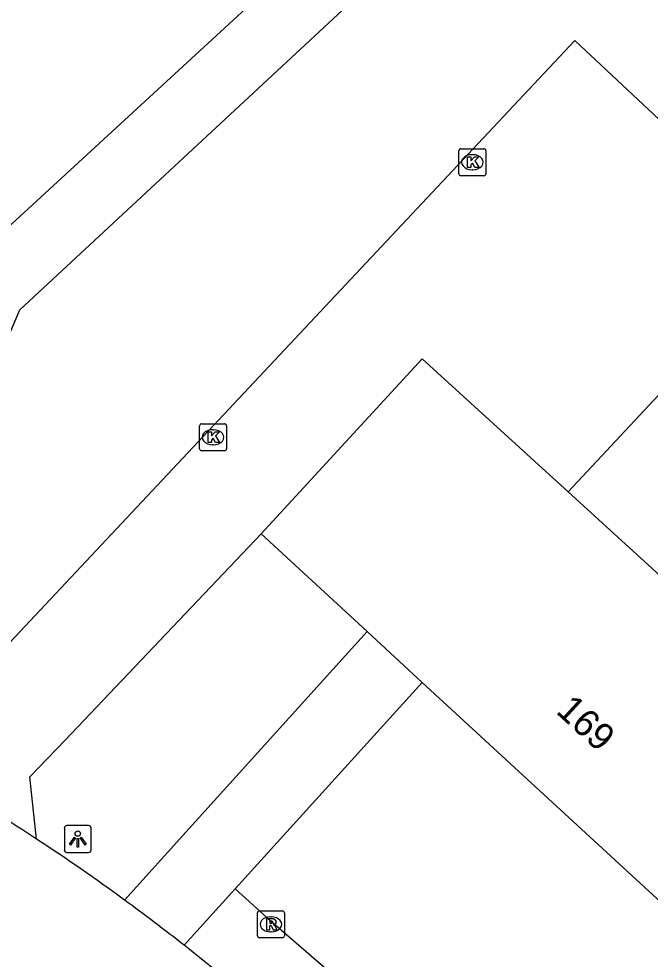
# Model space of a CAD drawing. Extents: x 160203 to 161526, y 379529 to 381797.
# Drawn here: x 160857.86 to 160881.3, y 381464.3 to 381499.19 of the extents above; entities that cross this region are included whole.
import ezdxf

# ---------------------------------------------------------------- set-up
doc = ezdxf.new("R2010")
doc.units = 0
for name, color, linetype in [('IMGEO_Grasland_overig', 7, 'Continuous'), ('IMGEO_Kolk', 7, 'Continuous'), ('IMGEO_Lichtpunt', 7, 'Continuous'), ('IMGEO_Pand', 7, 'Continuous'), ('IMGEO_Pand_nummerreeks', 7, 'Continuous'), ('IMGEO_Parkeervlak_open', 7, 'Continuous'), ('IMGEO_Rijbaan_lokaal_gesloten', 7, 'Continuous'), ('IMGEO_Rioolput', 7, 'Continuous'), ('IMGEO_Voetpad_open', 7, 'Continuous'), ('IMGEO_Waterloop', 7, 'Continuous')]:
    doc.layers.add(name, color=color, linetype=linetype)

msp = doc.modelspace()

# ---------------------------------------------------------------- linework, layer by layer
at = {"layer": 'IMGEO_Grasland_overig'}
msp.add_lwpolyline([(160865.887, 381466.901), (160867.061, 381465.849), (160874.741, 381459.219), (160875.912, 381458.343)], dxfattribs=at)
at = {"layer": 'IMGEO_Kolk'}
for p, q in [((160874.197, 381493.442), (160874.197, 381494.294)), ((160874.272, 381494.368), (160875.124, 381494.368)), ((160875.198, 381494.294), (160875.198, 381493.442)), ((160874.685, 381494.148), (160874.71, 381494.148)), ((160874.708, 381493.588), (160874.683, 381493.588)), ((160875.124, 381493.368), (160874.272, 381493.368)), ((160864.644, 381484.162), (160865.496, 381484.162)), ((160864.569, 381483.236), (160864.569, 381484.088)), ((160865.057, 381483.942), (160865.082, 381483.942)), ((160865.57, 381484.088), (160865.57, 381483.236)), ((160865.496, 381483.162), (160864.644, 381483.162)), ((160865.08, 381483.382), (160865.055, 381483.382))]:
    msp.add_line(p, q, dxfattribs=at)
for points in [[(160874.197, 381493.442), (160874.197, 381494.294)], [(160874.272, 381494.368), (160875.124, 381494.368)], [(160875.198, 381494.294), (160875.198, 381493.442)], [(160874.518, 381494.068), (160874.641, 381494.068), (160874.641, 381493.917), (160874.771, 381494.068), (160874.935, 381494.068), (160874.789, 381493.917), (160874.942, 381493.668), (160874.79, 381493.668), (160874.705, 381493.832), (160874.641, 381493.765), (160874.641, 381493.668), (160874.518, 381493.668), (160874.518, 381494.068)], [(160875.124, 381493.368), (160874.272, 381493.368)], [(160864.644, 381484.162), (160865.496, 381484.162)], [(160864.569, 381483.236), (160864.569, 381484.088)], [(160864.89, 381483.862), (160865.013, 381483.862), (160865.013, 381483.711), (160865.143, 381483.862), (160865.307, 381483.862), (160865.161, 381483.711), (160865.314, 381483.462), (160865.162, 381483.462), (160865.077, 381483.626), (160865.013, 381483.559), (160865.013, 381483.462), (160864.89, 381483.462), (160864.89, 381483.862)], [(160865.57, 381484.088), (160865.57, 381483.236)], [(160865.496, 381483.162), (160864.644, 381483.162)]]:
    msp.add_lwpolyline(points, dxfattribs=at)
for centre, start, end in [((160874.274, 381494.292), 91.552, 178.448), ((160874.274, 381494.292), 91.552, 178.448), ((160875.122, 381494.292), 1.552, 88.448), ((160875.122, 381494.292), 1.552, 88.448), ((160874.274, 381493.444), 181.552, 268.448), ((160874.274, 381493.444), 181.552, 268.448), ((160875.122, 381493.444), 271.552, 358.448), ((160875.122, 381493.444), 271.552, 358.448), ((160864.646, 381484.086), 91.552, 178.448), ((160864.646, 381484.086), 91.552, 178.448), ((160865.494, 381484.086), 1.552, 88.448), ((160865.494, 381484.086), 1.552, 88.448), ((160864.646, 381483.238), 181.552, 268.448), ((160864.646, 381483.238), 181.552, 268.448), ((160865.494, 381483.238), 271.552, 358.448), ((160865.494, 381483.238), 271.552, 358.448)]:
    msp.add_arc(centre, 0.0765, start, end, dxfattribs=at)
for centre, major_axis, ratio, start_param, end_param in [((160874.684, 381493.868), (-0.387, 0.002), 0.722429, 4.712389, 7.853982), ((160874.709, 381493.868), (-0.39, 0.002), 0.717154, 1.570796, 4.712389), ((160865.056, 381483.662), (-0.387, 0.002), 0.722429, 4.712389, 7.853982), ((160865.081, 381483.662), (-0.39, 0.002), 0.717154, 1.570796, 4.712389)]:
    msp.add_ellipse(centre, major_axis=major_axis, ratio=ratio, start_param=start_param, end_param=end_param, dxfattribs=at)
at = {"layer": 'IMGEO_Lichtpunt'}
for p, q in [((160859.551, 381469.158), (160859.551, 381468.351)), ((160859.551, 381469.158), (160859.551, 381468.351)), ((160860.453, 381469.253), (160859.645, 381469.253)), ((160860.453, 381469.253), (160859.645, 381469.253)), ((160860.547, 381468.351), (160860.547, 381469.158)), ((160860.547, 381468.351), (160860.547, 381469.158)), ((160859.645, 381468.257), (160860.453, 381468.257)), ((160859.645, 381468.257), (160860.453, 381468.257))]:
    msp.add_line(p, q, dxfattribs=at)
for points in [[(160859.925, 381468.822), (160859.964, 381468.794), (160859.776, 381468.532), (160859.738, 381468.559), (160859.925, 381468.822)], [(160860.137, 381468.794), (160860.175, 381468.821), (160860.362, 381468.559), (160860.323, 381468.531), (160860.137, 381468.794)], [(160860.027, 381468.774), (160860.074, 381468.774), (160860.074, 381468.452), (160860.027, 381468.452), (160860.027, 381468.774)]]:
    msp.add_lwpolyline(points, dxfattribs=at)
msp.add_circle((160860.05, 381468.956), 0.0994, dxfattribs=at)
for centre, start, end in [((160859.645, 381469.158), 90, 180), ((160859.645, 381469.158), 90, 180), ((160860.453, 381469.158), 0, 90), ((160860.453, 381469.158), 0, 90), ((160859.645, 381468.351), 180, 270), ((160859.645, 381468.351), 180, 270), ((160860.453, 381468.351), 270, 0), ((160860.453, 381468.351), 270, 360)]:
    msp.add_arc(centre, 0.0946, start, end, dxfattribs=at)
at = {"layer": 'IMGEO_Pand'}
for points in [[(160878.246, 381481.639), (160872.838, 381486.57), (160866.855, 381480.076)], [(160878.246, 381481.639), (160886.18, 381474.404), (160887.903, 381476.28), (160891.688, 381472.657), (160890.019, 381470.905), (160893.224, 381467.982), (160890.536, 381465.063), (160887.148, 381461.385), (160872.838, 381474.565)], [(160866.855, 381480.076), (160870.791, 381476.451)], [(160870.791, 381476.451), (160872.838, 381474.565)]]:
    msp.add_lwpolyline(points, dxfattribs=at)
at = {"layer": 'IMGEO_Parkeervlak_open'}
for points in [[(160852.239, 381472.497), (160854.749, 381473.091), (160856.568, 381475.028), (160878.497, 381498.378), (160886.709, 381490.688), (160878.246, 381481.639)], [(160858.52, 381468.754), (160858.276, 381471.06), (160859.578, 381472.429), (160866.855, 381480.076)]]:
    msp.add_lwpolyline(points, dxfattribs=at)
at = {"layer": 'IMGEO_Rijbaan_lokaal_gesloten'}
for centre, radius, start, end in [((160814.331, 381401.58), 80.406, 56.66204, 61.69701), ((160814.111, 381401.245), 80.807, 53.84533, 56.66219), ((160814.901, 381402.307), 79.482, 51.85349, 53.85314), ((160813.868, 381401.006), 81.144, 49.07117, 51.84759)]:
    msp.add_arc(centre, radius, start, end, dxfattribs=at)
at = {"layer": 'IMGEO_Rioolput'}
for p, q in [((160866.717, 381465.164), (160866.717, 381466.016)), ((160866.792, 381466.09), (160867.644, 381466.09)), ((160867.718, 381466.016), (160867.718, 381465.164)), ((160867.205, 381465.87), (160867.23, 381465.87)), ((160867.228, 381465.31), (160867.203, 381465.31)), ((160867.644, 381465.09), (160866.792, 381465.09))]:
    msp.add_line(p, q, dxfattribs=at)
for points in [[(160866.717, 381465.164), (160866.717, 381466.016)], [(160866.792, 381466.09), (160867.644, 381466.09)], [(160867.718, 381466.016), (160867.718, 381465.164)], [(160867.306, 381465.788), (160867.054, 381465.79), (160867.054, 381465.39)], [(160867.232, 381465.709), (160867.178, 381465.709), (160867.178, 381465.628)], [(160867.054, 381465.39), (160867.178, 381465.39), (160867.178, 381465.552), (160867.189, 381465.552)], [(160867.178, 381465.628), (160867.23, 381465.628)], [(160867.236, 381465.523), (160867.307, 381465.39), (160867.447, 381465.39), (160867.382, 381465.516)], [(160867.644, 381465.09), (160866.792, 381465.09)]]:
    msp.add_lwpolyline(points, dxfattribs=at)
for centre, radius, start, end in [((160866.794, 381466.014), 0.0765, 91.552, 178.448), ((160866.794, 381466.014), 0.0765, 91.552, 178.448), ((160867.642, 381466.014), 0.0765, 1.552, 88.448), ((160867.642, 381466.014), 0.0765, 1.552, 88.448), ((160867.238, 381465.613), 0.0964, 77.0061, 93.1865), ((160867.252, 381465.67), 0.0378, 276.6634, 79.6772), ((160867.305, 381465.678), 0.109, 350.3612, 89.416), ((160867.303, 381465.678), 0.112, 277.5842, 350.9817), ((160867.188, 381465.499), 0.0533, 26.0293, 88.6989), ((160867.214, 381465.817), 0.19, 274.7715, 282.9687), ((160867.287, 381465.463), 0.108, 29.5134, 73.7905), ((160866.794, 381465.166), 0.0765, 181.552, 268.448), ((160866.794, 381465.166), 0.0765, 181.552, 268.448), ((160867.642, 381465.166), 0.0765, 271.552, 358.448), ((160867.642, 381465.166), 0.0765, 271.552, 358.448)]:
    msp.add_arc(centre, radius, start, end, dxfattribs=at)
for centre, major_axis, ratio, start_param, end_param in [((160867.204, 381465.59), (-0.387, 0.002), 0.722429, 4.712389, 7.853982), ((160867.229, 381465.59), (-0.39, 0.002), 0.717154, 1.570796, 4.712389)]:
    msp.add_ellipse(centre, major_axis=major_axis, ratio=ratio, start_param=start_param, end_param=end_param, dxfattribs=at)
at = {"layer": 'IMGEO_Voetpad_open'}
for points in [[(160870.791, 381476.451), (160863.833, 381468.756), (160861.784, 381466.49)], [(160872.838, 381474.565), (160865.887, 381466.901)], [(160865.887, 381466.901), (160863.995, 381464.815)]]:
    msp.add_lwpolyline(points, dxfattribs=at)
at = {"layer": 'IMGEO_Waterloop'}
for points in [[(160849.017, 381474.358), (160852.468, 381475.687), (160853.366, 381477.791), (160857.893, 381488.392), (160870.4, 381500), (160877.775, 381506.845), (160880.587, 381511.607)], [(160875.643, 381510.142), (160876.176, 381509.463), (160876.094, 381508.603), (160866.739, 381500), (160855.41, 381489.581), (160847.377, 381482.556)]]:
    msp.add_lwpolyline(points, dxfattribs=at)

# ---------------------------------------------------------------- texts
at = {"layer": 'IMGEO_Pand_nummerreeks'}
msp.add_text('169', height=1, rotation=317.3532, dxfattribs=at).set_placement((160877.762, 381473.457))

doc.saveas('drawing.dxf')
